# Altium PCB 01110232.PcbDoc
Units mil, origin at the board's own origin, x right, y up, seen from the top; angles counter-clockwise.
Board outline 3350 x 4325 mil, 2 copper layers (Top Layer, Bottom Layer); 124 components, 54 nets, 280 pads, 11 vias.
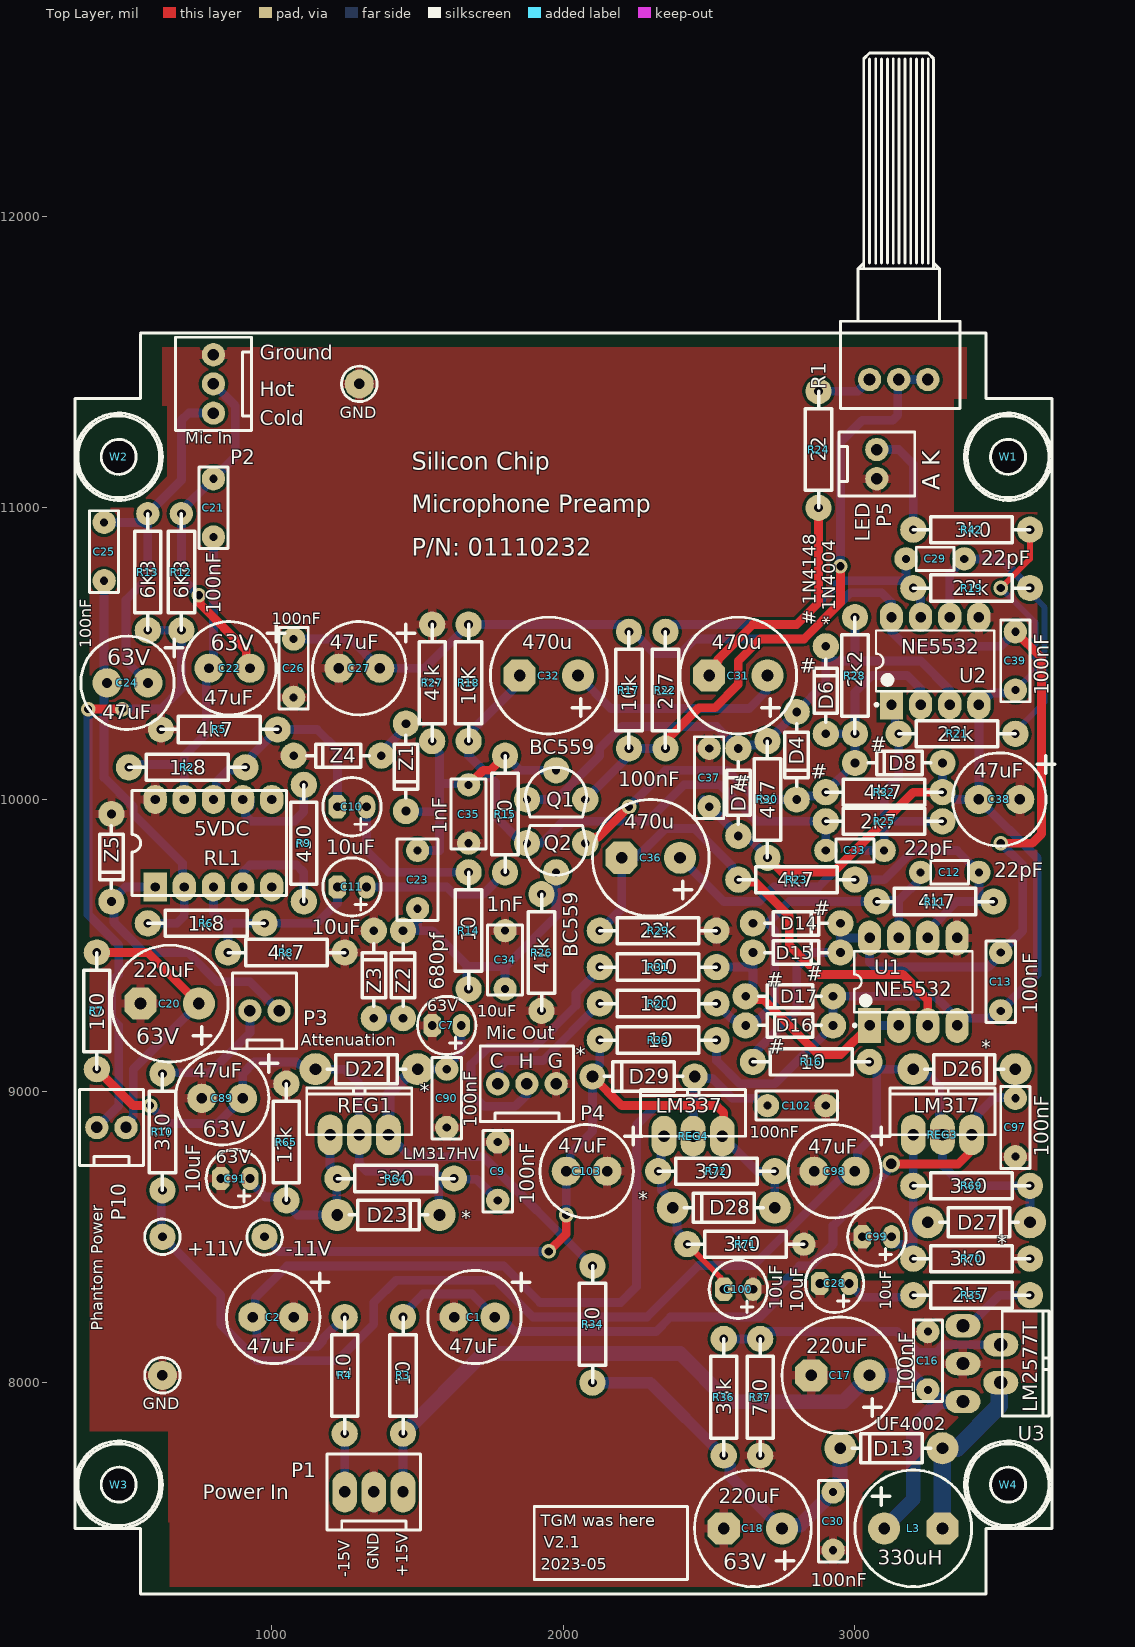
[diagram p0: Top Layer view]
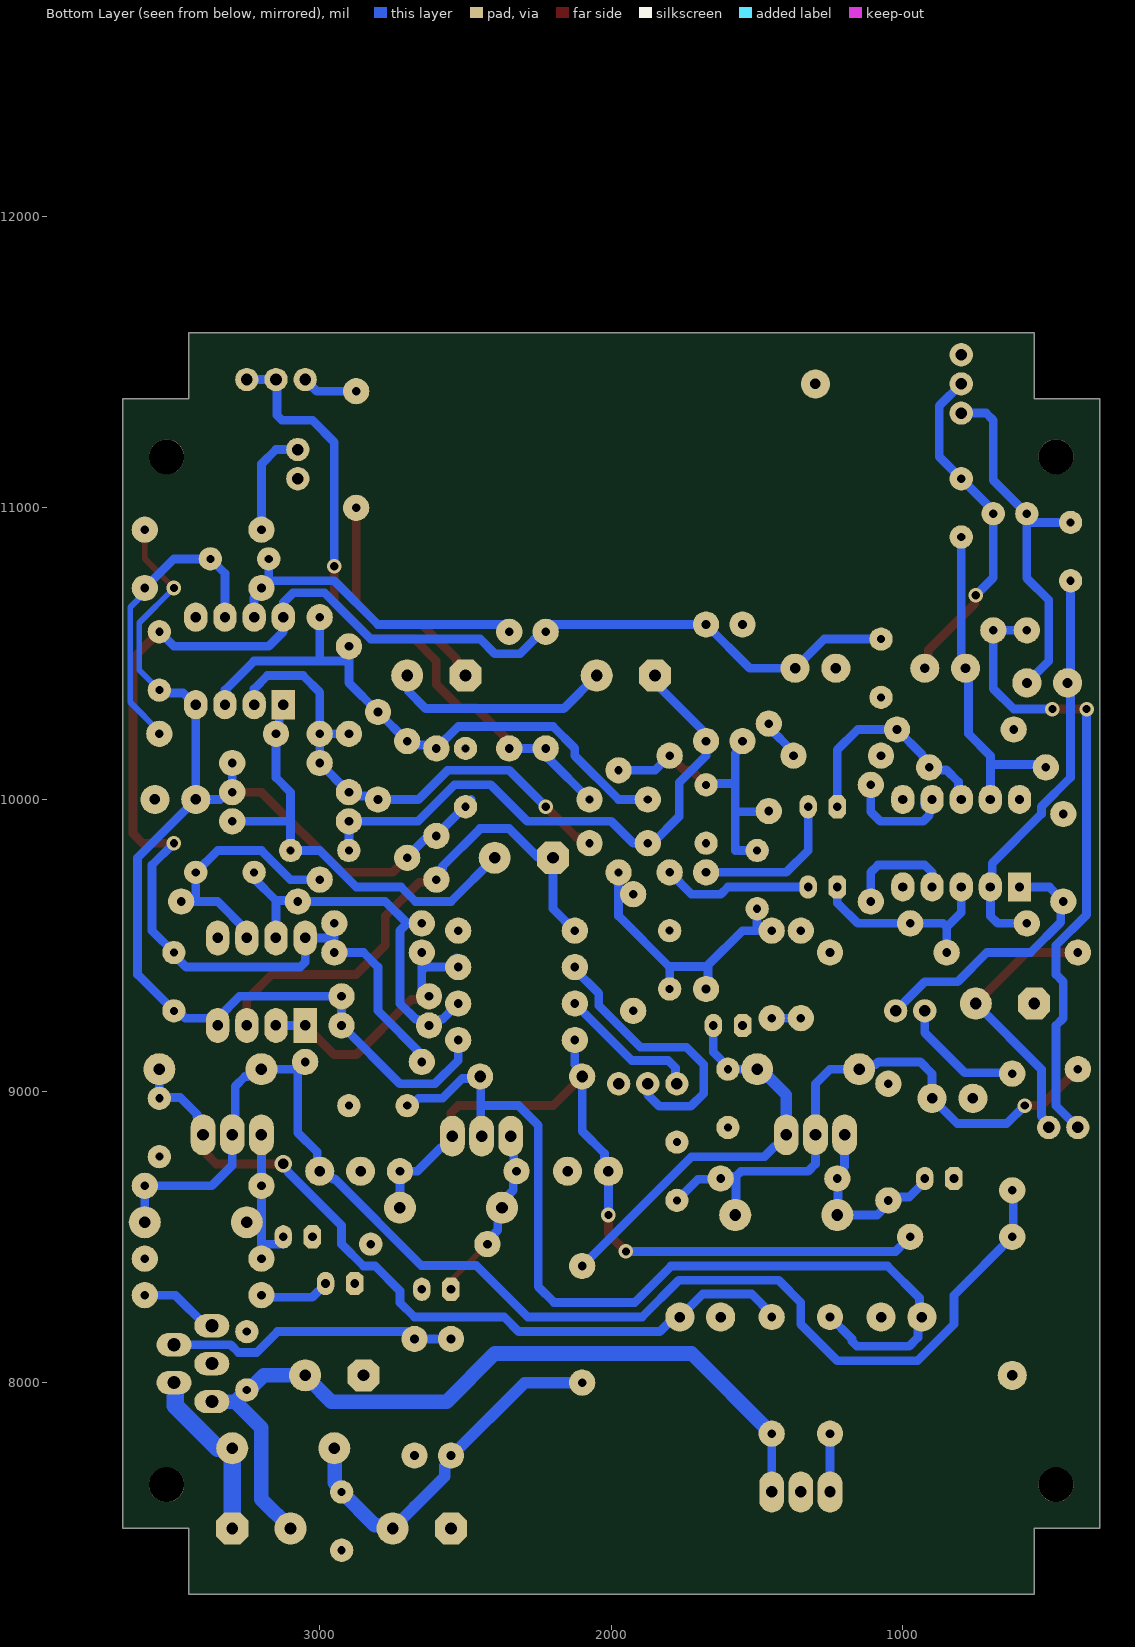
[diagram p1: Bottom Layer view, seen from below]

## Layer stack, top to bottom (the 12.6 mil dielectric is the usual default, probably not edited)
Top Solder: solder mask 0.4, Solder Resist, Dk 3.5
Top Layer: signal copper 1.4
Dielectric1: dielectric 12.6, FR-4, Dk 4.8
Bottom Layer: signal copper 1.4
Bottom Solder: solder mask 0.4, Solder Resist, Dk 3.5

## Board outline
325,7500 550,7500 550,7275 3450,7275 3450,7500 3675,7500 3675,11375 3450,11375 3450,11600 2800,11600 850,11600 550,11600 550,11375 325,11375

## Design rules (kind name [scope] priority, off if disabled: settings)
Clearance Clearance_1 [All] p1: gap=10 ignorepadtopadclearanceinfootprint=TRUE
Clearance Clearance_poly [(IsRegion)] p2: gap=10 ignorepadtopadclearanceinfootprint=FALSE
DiffPairsRouting [All] p1: maxlimit=10 minlimit=10 mostfreqgap=10 toplayer_minwidth=15 toplayer_maxwidth=15 toplayer_prefwidth=15 bottomlayer_minwidth=15 bottomlayer_maxwidth=15 bottomlayer_prefwidth=15 substack1={E4759729-C15E-44EF-B839-1660CB1699A4} toplayer_{e4759729-c15e-44ef-b839-1660cb1699a4}_minwidth=15 toplayer_{e4759729-c15e-44ef-b839-1660cb1699a4}_maxwidth=15 toplayer_{e4759729-c15e-44ef-b839-1660cb1699a4}_prefwidth=15 bottomlayer_{e4759729-c15e-44ef-b839-1660cb1699a4}_minwidth=15 bottomlayer_{e4759729-c15e-44ef-b839-1660cb1699a4}_maxwidth=15 bottomlayer_{e4759729-c15e-44ef-b839-1660cb1699a4}_prefwidth=15 substack2={AF7D8FCE-D8A9-40D7-8453-C7F108753530} toplayer_{af7d8fce-d8a9-40d7-8453-c7f108753530}_minwidth=15 toplayer_{af7d8fce-d8a9-40d7-8453-c7f108753530}_maxwidth=15 toplayer_{af7d8fce-d8a9-40d7-8453-c7f108753530}_prefwidth=15 bottomlayer_{af7d8fce-d8a9-40d7-8453-c7f108753530}_minwidth=15 bottomlayer_{af7d8fce-d8a9-40d7-8453-c7f108753530}_maxwidth=15 bottomlayer_{af7d8fce-d8a9-40d7-8453-c7f108753530}_prefwidth=15 maxuncoupledlength=500
Height [All] p1: minheight=0 maxheight=1130 prefheight=500
HoleSize [All] p1: absolutevalues=TRUE maxlimit=400 minlimit=1 maxpercent=80.000 minpercent=20.000
PlaneConnect [All] p1: planeconnectstyle=Relief reliefexpansion=20 reliefentries=4 reliefconductorwidth=30 reliefairgap=10
PolygonConnect [All] p1: connectstyle=Relief reliefconductorwidth=30 reliefentries=4 polygonreliefangle="90 Angle" airgapwidth=10
RoutingVias [All] p1: holewidth=16 width=32 viastyle="Through Hole" minholewidth=8 minwidth=16 maxholewidth=200 maxwidth=200
SilkToSolderMaskClearance SilkscreenOverComponentPads [IsPad] p1: minsilkscreentomaskgap=10 clearancetoexposedcopper=TRUE
SolderMaskExpansion [All] p1: expansion=4 istentingtop=FALSE
Width [All] p1: maxlimit=250 minlimit=10 preferedwidth=40 substack1={E4759729-C15E-44EF-B839-1660CB1699A4} substack2={AF7D8FCE-D8A9-40D7-8453-C7F108753530}
25 further rules are at their usual default settings.

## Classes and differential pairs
component class "Mic Interface": C10 C11 C12 C13 C20 C21 C22 C23 C24 C25 C26 C27 C29 C31 C32 C33 C34 C35 C36 C37 C38 C39 D4 D6 D7 D8 D14 D15 D16 D17 P2 P3 P4 P5 P10 Q1 Q2 R1 R2 R5 R6 R7 R8 R9 R10 R11 R12 R13 R14 R15 R16 R17 R18 R19 R20 R21 R22 R23 R24 R25 R26 R27 R28 R29 R30 R31 R32 R33 R42 RL1 U1 U2 Z1 Z2 Z3 Z4 Z5
component class "Power Supply": C1 C2 C7 C9 C16 C17 C18 C28 C30 C89 C90 C91 C97 C98 C99 C100 C102 C103 D13 D22 D23 D26 D27 D28 D29 F2 L3 L6 P1 R3 R4 R34 R35 R36 R37 R64 R65 R69 R70 R71 R72 REG1 REG3 REG4 U3 W1 W2 W3 W4

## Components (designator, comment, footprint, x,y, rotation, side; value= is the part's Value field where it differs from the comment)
C1 "47uF" RB3.5/8mm 1765,8225 r180 top
C2 "47uF" RB3.5/8mm 1075,8225 r180 top
C7 "10uF" RB.1/.2-PTH 1650,9225 r0 top
C9 "100nF" AXIAL0.2-2.5mm-CAP 1775,8625 r90 top
C10 "10uF" RB.1/.2-PTH 1325,9975 r0 top
C11 "10uF" RB.1/.2-PTH 1325,9700 r0 top
C12 "22pF" AXIAL0.2 3225,9750 r0 top
C13 "100nF" AXIAL0.2-2.5mm-CAP 3500,9475 r270 top
C16 "100nF" AXIAL0.2-2.5mm-CAP 3250,7975 r90 top
C17 "220uF" RB.2/.4 3050,8025 r0 top
C18 "220uF" RB.2/.4 2750,7500 r0 top
C20 "220uF" RB.2/.4 750,9300 r0 top
C21 "100nF" AXIAL0.2-2.5mm-CAP 800,11100 r270 top
C22 "47uF" RB3.5/8MM 925,10450 r180 top
C23 "680pf" AXIAL0.2-3.5mm-CAP 1500,9825 r270 top
C24 "47uF" RB3.5/8MM 575,10400 r180 top
C25 "100nF" AXIAL0.2-2.5mm-CAP 425,10950 r270 top
C26 "100nF" AXIAL0.2-2.5mm-CAP 1075,10550 r270 top
C27 "47uF" RB3.5/8mm 1370,10450 r180 top
C28 "10uF" RB.1/.2-PTH 2980,8340 r0 top
C29 "22pF" AXIAL0.2 3175,10825 r0 top
C30 "100nF" AXIAL0.2-2.5mm-CAP 2925,7625 r270 top
C31 "470u" RB.2/.4 2700,10425 r0 top
C32 "470u" RB.2/.4 2050,10425 r0 top
C33 "22pF" AXIAL0.2 2900,9825 r0 top
C34 "1nF" AXIAL0.2-CAP 1800,9550 r270 top
C35 "1nF" AXIAL0.2-CAP 1675,9850 r90 top
C36 "470u" RB.2/.4 2400,9800 r0 top
C37 "100nF" AXIAL0.2-2.5mm-CAP 2500,10175 r270 top
C38 "47uF" RB3.5/8mm 3565,10000 r180 top
C39 "100nF" AXIAL0.2-2.5mm-CAP 3550,10575 r270 top
C89 "47uF" RB3.5/8mm 900,8975 r180 top
C90 "100nF" AXIAL0.2-2.5mm-CAP 1600,9075 r270 top
C91 "10uF" RB.1/.2-PTH 925,8700 r0 top
C97 "100nF" AXIAL0.2-2.5mm-CAP 3550,8975 r270 top
C98 "47uF" RB3.5/8mm 3000,8725 r180 top
C99 "10uF" RB.1/.2-PTH 3125,8500 r0 top
C100 "10uF" RB.1/.2-PTH 2650,8320 r0 top
C102 "100nF" AXIAL0.2-2.5mm-CAP 2900,8950 r180 top
C103 "47uF" RB3.5/8mm 2150,8725 r180 top
D4 "1N914" "DIODE0.3-TH - AK" 2800,10300 r270 top
D6 "1N914" "DIODE0.3-TH - AK" 2900,10225 r90 top
D7 "1N914" "DIODE0.3-TH - AK" 2600,9875 r90 top
D8 "1N914" "DIODE0.3-TH - AK" 3300,10125 r180 top
D13 "UF4002" DIODE0.35-TH#1 3300,7775 r180 top
D14 "1N914" "DIODE0.3-TH - AK" 2650,9575 r0 top
D15 "1N914" "DIODE0.3-TH - AK" 2650,9475 r0 top
D16 "1N914" "DIODE0.3-TH - AK" 2925,9225 r180 top
D17 "1N914" "DIODE0.3-TH - AK" 2925,9325 r180 top
D22 "1N4004" DIODE0.35-TH#1 1150,9075 r0 top
D23 "1N4004" DIODE0.35-TH#1 1225,8575 r0 top
D26 "1N4004" DIODE0.35-TH#1 3200,9075 r0 top
D27 "1N4004" DIODE0.35-TH#1 3250,8550 r0 top
D28 "1N4004" DIODE0.35-TH#1 2725,8600 r180 top
D29 "1N4004" DIODE0.35-TH#2 2450,9050 r180 top
L3 "330uH" RB.2/.4 3100,7500 r180 top
P1 "Power In" "Header 3 SIL" 1450,7625 r180 top
P2 "Mic In" "HEADER 3 SIL" 800,11525 r270 top
P3 "Attenuation" "HEADER 2 SIL" 1025,9275 r180 top
P4 "Mic Out" "HEADER 3 SIL" 1975,9025 r180 top
P5 "LED" "Header 2 SIL" 3075,11100 r90 top
P10 "Phantom Power" "HEADER 2 SIL" 500,8875 r180 top
Q1 "BC559" TO-92BIG 1975,10100 r90 top
Q2 "BC559" TO-92BIG 1975,9750 r270 top
R1 "10K Reverse Log" "POT_Small_Single - TT Single Horizontal" 3150,11440 r180 top
R2 "1k8" AXIAL0.4#1 910,10110 r180 top
R3 "10" AXIAL0.4#1 1450,7825 r90 top
R4 "10" AXIAL0.4#1 1250,8225 r270 top
R5 "4k7" AXIAL0.4#1 1020,10240 r180 top
R6 "1k8" AXIAL0.4#1 975,9575 r180 top
R7 "100" AXIAL0.4#1 400,9075 r90 top
R8 "4k7" AXIAL0.4#1 850,9475 r0 top
R9 "430" AXIAL0.4#1 1110,10050 r270 top
R10 "330" AXIAL0.4#1 625,9059.69 r270 top
R11 "4k7" AXIAL0.4#1 3075,9650 r0 top
R12 "6K8" AXIAL0.4#2 690,10980 r270 top
R13 "6K8" AXIAL0.4#2 575,10980 r270 top
R14 "10" AXIAL0.4#1 1675,9750 r270 top
R15 "10" AXIAL0.4#1 1800,9750 r90 top
R16 "10" AXIAL0.4#1 3050,9100 r180 top
R17 "10k" AXIAL0.4#1 2225,10175 r90 top
R18 "10K" AXIAL0.4#1 1675,10200 r90 top
R19 "22k" AXIAL0.4#1 3200,10725 r0 top
R20 "100" AXIAL0.4#1 2525,9300 r180 top
R21 "22k" AXIAL0.4#1 3550,10225 r180 top
R22 "2k7" AXIAL0.4#1 2350,10175 r90 top
R23 "4k7" AXIAL0.4#1 3000,9725 r180 top
R24 "22" AXIAL0.4#1 2875,11400 r270 top
R25 "2k7" AXIAL0.4#1 2900,9925 r0 top
R26 "47k" AXIAL0.4#1 1925,9675 r270 top
R27 "47k" AXIAL0.4#1 1550,10200 r90 top
R28 "2k2" AXIAL0.4#1 3000,10625 r270 top
R29 "22k" AXIAL0.4#1 2525,9550 r180 top
R30 "4K7" AXIAL0.4#1 2700,9800 r90 top
R31 "100" AXIAL0.4#1 2525,9425 r180 top
R32 "4K7" AXIAL0.4#1 3300,10025 r180 top
R33 "10" AXIAL0.4#1 2125,9175 r0 top
R34 "10" AXIAL0.4#1 2100,8000 r90 top
R35 "2k7" AXIAL0.4#1 3200,8300 r0 top
R36 "33k" AXIAL0.4#1 2550,8150 r270 top
R37 "750" AXIAL0.4#1 2675,7750 r90 top
R42 "3k0" AXIAL0.4#1 3200,10925 r0 top
R64 "330" AXIAL0.4#1 1225,8700 r0 top
R65 "12k" AXIAL0.4#1 1050,9025 r270 top
R69 "390" AXIAL0.4#1 3200,8675 r0 top
R70 "3k0" AXIAL0.4#1 3600,8425 r180 top
R71 "3k0" AXIAL0.4#3 2425,8475 r0 top
R72 "390" AXIAL0.4#1 2725,8725 r180 top
REG1 "LM317HV" TO-220-REG 1300,8850 r0 top
REG3 "LM317" TO-220-REG 3300,8850 r0 top
REG4 "LM337" TO-220-REG 2444.99,8845 r0 top
RL1 "5VDC" DIP10 600,9700 r90 top
U1 "NE5532" DIP-8#1 3200,9375 r90 top
U2 "NE5532" DIP-8#2 3275,10475 r90 top
U3 "LM2577T" "TO-220 - 5PIN" 3520,8065 r270 top
W1 "Washer" "M3 Crinkle" 3525,11175 r0 top
W2 "Washer" "M3 Crinkle" 475,11175 r0 top
W3 "Washer" "M3 Crinkle" 475,7650 r0 top
W4 "Washer" "M3 Crinkle" 3525,7650 r0 top
Z1 "6V8" "DIODE0.3-TH - AK" 1460,10260 r270 top
Z2 "6V8" "DIODE0.3-TH - AK" 1450,9250 r90 top
Z3 "6V8" "DIODE0.3-TH - AK" 1350,9250 r90 top
Z4 "6V8" "DIODE0.3-TH - AK" 1375,10150 r180 top
Z5 "6V8" "DIODE0.3-TH - AK" 450,9950 r270 top

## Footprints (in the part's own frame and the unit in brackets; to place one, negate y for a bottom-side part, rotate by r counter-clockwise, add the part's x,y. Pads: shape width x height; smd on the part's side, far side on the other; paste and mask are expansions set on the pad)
AXIAL0.2 [mil]
  round 80 hole 28: 1(0,0) 2(200,0)
  silkscreen extent 35,-40 165,40, body extent 30,-45 170,45, height 200
AXIAL0.2-2.5mm-CAP [mil]
  round 80 hole 28: 1(0,0) 2(200,0)
  silkscreen extent -40,-50 240,50, body extent -40,-50 240,50, height 200
AXIAL0.2-3.5mm-CAP [mil]
  round 80 hole 28: 1(0,0) 2(200,0)
  silkscreen extent -40,-70 240,70, body extent -40,-70 240,70, height 200
AXIAL0.2-CAP [mil]
  round 80 hole 28: 1(0,0) 2(200,0)
  silkscreen extent -20,-60 220,60, body extent -25,-65 225,65, height 200
AXIAL0.4#1 [mil] "resistor"
  round 90 hole 30: 1(0,0) 2(400,0)
  silkscreen extent 0,-45 400,45, body extent -5,-50 405,50, height 100
AXIAL0.4#2 [mil] "resistor"
  round 80 hole 30: 1(0,0)
  round 90 hole 30: 2(400,0)
  silkscreen extent 0,-45 400,45, body extent -5,-50 405,50, height 100
AXIAL0.4#3 [mil] "resistor"
  round 90 hole 30: 1(0,0)
  round 80 hole 30: 2(400,0)
  silkscreen extent 0,-45 400,45, body extent -5,-50 405,50, height 100
"DIODE0.3-TH - AK" [mil] "DO-35 Footprint"
  round 90 hole 30: A(0,0) K(300,0)
  silkscreen extent 40,-40 255,40, body extent -15,-40 315,40, height 95
DIODE0.35-TH#1 [mil]
  round 110 hole 40: 1(0,0) 2(350,0)
  silkscreen extent 40,-50 310,50, body extent -15,-55 365,55, height 110
DIODE0.35-TH#2 [mil]
  round 90 hole 40: 1(0,0) 2(350,0)
  silkscreen extent 40,-50 310,50, body extent -15,-55 365,55, height 110
DIP10 [mil] "DPDT signal relay"
  rect 100x80 hole 32: 1(0,0)
  oval 100x80 hole 32: 2(0,-100) 3(0,-200) 4(0,-300) 5(0,-400) 6(300,-400) 7(300,-300) 8(300,-200) 9(300,-100) 10(300,0)
  silkscreen extent -30,-450 330,80, body extent -30,-450 330,80, height 300
DIP-8#1 [mil] "DIP; 8 Leads; Row Spacing 7.62 mm; Pitch 2.54 mm"
  rect 120x80 hole 36: 1(-150,150)
  oval 120x80 hole 36: 2(-150,50) 3(-150,-50) 4(-150,-150) 5(150,-150) 6(150,-50) 7(150,50) 8(150,150)
  silkscreen extent -155,-203 104,206, body extent -142,-203 142,203, height 200
DIP-8#2 [mil] "DIP; 8 Leads; Row Spacing 7.62 mm; Pitch 2.54 mm"
  rect 100x80 hole 35.43: 1(-150,150)
  oval 100x80 hole 35.43: 2(-150,50) 3(-150,-50) 4(-150,-150) 5(150,-150) 6(150,-50) 7(150,50) 8(150,150)
  silkscreen extent -155,-203 104,206, body extent -142,-203 142,203, height 200
"HEADER 2 SIL" [mil] "Altronics P5494"
  round 80 hole 39.37: 1(0,0) 2(100,0)
  silkscreen extent -60,-130 160,130, body extent -65,-135 160,135, height 460
"Header 2 SIL" [mil] "Altronics P5494"
  round 80 hole 39.37: 1(0,0) 2(100,0)
  silkscreen extent -60,-130 160,130, body extent -65,-135 160,135, height 460
"Header 3 SIL" [mil] "Altronics P5494"
  oval 85x140 hole 39.37: 1(0,0) 2(100,0) 3(200,0)
  silkscreen extent -60,-130 260,130, body extent -65,-135 260,135, height 460
"HEADER 3 SIL" [mil] "Altronics P5494"
  round 80 hole 39.37: 1(0,0) 2(100,0) 3(200,0)
  silkscreen extent -60,-130 260,130, body extent -65,-135 260,135, height 460
"M3 Crinkle" [mil] "M3 Crinkle Washer"
  silkscreen extent -140,-140 140,140, body extent -140,-140 140,140, height 20
"POT_Small_Single - TT Single Horizontal" [mil] "Bourns PTV111-1 Single Turn Small"
  round 80 hole 40: 1(-100,0) 2(0,0) 3(100,0)
  silkscreen extent -210,-1120 200,100, body extent -210,-1125 200,100, height 500
RB3.5/8mm [mil]
  round 100 hole 36: 1(0,0) 2(140,0)
  silkscreen extent -120,-160 230,160, body extent -90,-160 230,160, height 450
RB3.5/8MM [mil]
  round 100 hole 34: 1(0,0) 2(140,0)
  silkscreen extent -120,-160 230,160, body extent -90,-160 230,160, height 450
RB.1/.2-PTH [mil]
  oval 60x80 hole 30: 1(0,0)
  oct 60x80 hole 30: 2(-100,0)
  silkscreen extent -150,-100 50,100, body extent -150,-100 50,100, height 300
RB.2/.4 [mil]
  round 110 hole 40: 1(0,0)
  oct 110x110 hole 40: 2(-200,0)
  silkscreen extent -300,-200 100,200, body extent -300,-200 100,200, height 1000
TO-92BIG [mil]
  round 90 hole 28: B(0,0) C(-100,100) E(-100,-100)
  silkscreen extent -160,-105 10,105, body extent -160,-110 10,110, height 500
"TO-220 - 5PIN" [mil]
  oval 80x120 hole 45: 1(-130,-150) 2(-65,-20) 3(0,-150) 4(65,-20) 5(130,-150)
  silkscreen extent -180,-15 180,145, body extent -180,-160 180,145, height 950
TO-220-REG [mil]
  oval 85x140 hole 40: 1(-100,0) 2(-0.12,0.2) 3(100,0)
  silkscreen extent -180,0 180,160, body extent -180,0 180,160, height 800

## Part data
C1 C2 C27 C38 C89 C98 C103: library part "CAPACITOR POL", "Altronics p/n R5108"
C7 C91: library part CAPACITOR, "Altronics p/n R4768"
C9 C13 C16 C21 C25 C26 C30 C37 C39 C90 C97 C102: library part CAP, "Altronics p/n R3025B"
C10 C11 C28 C99 C100: library part CAPACITOR, "Altronics p/n R6067"
C12 C29 C33: library part CAP, "Altronics p/n R2814"
C17 C18 C20: library part "CAPACITOR POL", "Altronics p/n R5148"
C22 C24: library part CAPACITOR, "Altronics p/n R5108"
C23: library part CAP, "Mouser p/n 810-FA28C0G1H68100"
C31 C32 C36: library part CAPACITOR, "Altronics p/n R5164"
C34 C35: library part CAP, "Altronics p/n R3001B"
D4 D6 D7 D8 D14 D15 D16 D17: library part DIODE, "Altronics p/n Z0101"
D13: library part DIODE_Numbered, "Altronics p/n Z0030"
D22 D26: library part DIODE_Numbered, "Altronics p/n Z0109"
D23 D27 D28 D29: library part DIODE, "Altronics p/n Z0109"
L3: library part INDUCTOR, "Altronics p/n L6227"
P1 P2 P4: library part "Header 3", "Altronics p/n  P5493 + P5473"
P3 P5 P10: library part CON2, "Altronics p/n  P5492 + P5472"
Q1 Q2: library part PNP, "Altronics p/n Z1057"
R1: library part POT-SINGLE, "Mouser p/n  858-P091NFC25CR10K or 652-PTD9012015FC103"
R2 R6: library part RES2, "Altronics p/n R7564"
R3 R4 R34: library part RES2, "Altronics p/n Z7510"
R5 R8 R11 R23 R30 R32: library part RES2, "Altronics p/n R7574"
R7: library part RES2, "Altronics p/n Z7534"
R9: library part RES2, "Altronics p/n R7551"
R10: library part RES2, "Altronics p/n R7538"
R12 R13: library part RES2, "Altronics p/n R7778"
R14 R15 R16 R33: library part RES2, "Altronics p/n R7510"
R17 R18: library part RES2, "Altronics p/n R7582"
R19 R21 R29: library part RES2, "Altronics p/n R7590"
R20 R31: library part RES2, "Altronics p/n R7534"
R22 R25 R35: library part RES2, "Altronics p/n R7568"
R24: library part RES2, "Altronics p/n R7518"
R26 R27: library part RES2, "Altronics p/n R7598"
R28: library part RES2, "Altronics p/n R7566"
R36: library part RES2, "Altronics p/n R7594"
R37: library part RES2, "Altronics p/n R7555"
R42 R70 R71: library part RES2, "Altronics p/n R7569"
R64: library part RES2, "Altronics p/n R7546"
R65: library part RES2, "Altronics p/n R7584"
R69 R72: library part RES2, "Altronics p/n R7548"
REG1: library part LM317, "Altronics p/n Z0545"
REG3: "Altronics p/n Z0545"
REG4: "Altronics p/n Z0562"
RL1: library part RELAY-DPDT_OMRON, "Altronics p/n S4128B"
U1 U2: library part LF353, "Altronics p/n Z2785"
U3: library part LM2577T-ADJ/NOPB, "Jaycar p/n ZV1640", Manufacturer="National Semiconductor", PackageTopMarking=NSUZXYTTE#*LM2577T*-ADJ*P+, PowerWise=N, Supplier Part Number 1=LM2577T-ADJ-ND
W1 W2 W3 W4: "Altronics p/n H3185"
Z1 Z2 Z3 Z4 Z5: library part ZENER2, "Altronics p/n Z0320"

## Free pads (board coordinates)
  round 120 hole 120: 3(475,7650) 3(475,11175) 3(3525,7650) 3(3525,11175)
  round 100 hole 36: 4(625,8025) 4(1300,11425)
  round 90 hole 30: 6(625,8500) 7(975,8500)

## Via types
v1: diameter 50, hole 28, Top Layer to Bottom Layer, 10 vias
v2: diameter 60, hole 36, Top Layer to Bottom Layer, 1 vias

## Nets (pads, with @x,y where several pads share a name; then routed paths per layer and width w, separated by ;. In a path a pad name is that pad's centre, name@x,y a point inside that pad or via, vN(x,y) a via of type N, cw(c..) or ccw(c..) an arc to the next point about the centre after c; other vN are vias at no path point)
48V: C9.1 C89.1 D22.1 D23.2 R7.1 R64.2 REG1.2 | length 2080.7
  Top Layer w30: R7.1 525,8950 v1(582.37,8950)
  Bottom Layer w30: v1(582.37,8950) 643.84,8888.53 813.53,8888.53 C89.1 900,9059.69 940.31,9100 1084.61,9100 1094.3,9090.31 1134.69,9090.31 D22.1 1250,9075 1299.88,9025.12 REG1.2 1299.88,8750.12 1325,8725 1554.93,8725 1572.5,8707.43 ; D23.2 1572.5,8577.5 1572.5,8707.43 ; C9.1 1702.5,8697.5 1627.5,8697.5 R64.2 1617.57,8707.43 1572.5,8707.43
+DC_In: C16.1 C17.1 L3.1 P1.1 R3.1 U3.5 | length 2874.4
  Bottom Layer w30: P1.1 R3.1
  Bottom Layer w50: R3.1 1725,8100 2400,8100 2565,7935 2960,7935 3035,8010 C17.1@3040,8010 ; C17.1 3191.88,8025 3241.88,7975 C16.1 3250,7974.48 3289.48,7935 ; L3.1 3200,7600 3200,7845.52 3289.48,7935 ; U3.5 3289.48,7935
+V_filt_2: C13.1 C26.1 C27.1 C39.1 D14.K D15.K R16.2 R17.2 R18.2 U1.8 U2.8 | length 5510.6
  Top Layer w30: U2.8 U2.8@3125,10635 ; v1(3500,9850) 3607.57,9850 3640,9882.43 3640,10485 C39.1
  Bottom Layer w30: C26.1 1270,10550 C27.1 ; C27.1@1375,10450 1525,10450 R18.2 2225,10600 2225,10588.39 2313.39,10500 2400,10500 2450,10550 2825,10550 2983.76,10708.76 3091.24,10708.76 3125,10675 U2.8 3125,10575 3175,10525 3500,10525 C39.1 ; R16.2@2637.38,9121.14 2646.14,9121.14 2800,9275 2800,9425 2850,9475 D15.K 2950,9525 ; D14.K 2950,9525 ; U2.8@3146.66,10628.34 U2.8@3150,10625 ; v1(3500,9850) 3575,9775 3575,9550 C13.1 3500,9467.57 3457.43,9425 3067.57,9425 3050,9442.57 U1.8 2950,9525
+VREG: C98.1 D26.1 D27.2 pad.6 R10.2 R16.1 R69.2 REG3.2 | length 4575.4
  Bottom Layer w30: R10.2 621.21,8655.9 621.21,8503.79 825,8300 825,8200 950,8075 1225,8075 1350,8200 1350,8275 1426.3,8351.3 1768.66,8351.3 1894.96,8225 2286.48,8225 2463.23,8401.75 2651.75,8401.75 2948.65,8698.65 2954.71,8698.65 2981.06,8725 C98.1 3008.69,8733.69 3008.69,8790.66 3075,8856.98 R16.1@3075,9075 ; R16.1 R16.1@3075,9075 ; D27.2 R69.2 3370,8675 3300,8745 3300,8850 3289.48,8860.52 3289.48,9016.77 3256.34,9049.91 3246.73,9049.91 3221.65,9075 D26.1 R16.1@3075,9075
-DC_In: P1.3 R4.2 | length 200
  Bottom Layer w30: P1.3 R4.2
-V_filt_2: C13.2 C37.2 C38.2 C39.2 D7.A D8.A D16.A D17.A R30.1 R32.1 R33.2 R42.2 U1.4 U2.4 | length 4629.4
  Top Layer w20: v1(3500,10725) 3600,10825 R42.2
  Top Layer w30: R30.1 2750,9750 2925,9750 3200,10025 R32.1 ; D16.A@2925,9210 D16.A
  Bottom Layer w20: v1(3500,10725) 3618.75,10606.25 3618.75,10443.75 C39.2
  Bottom Layer w30: C37.2@2480,10000 2480,9997.5 2600,9877.5 D7.A 2611.48,9863.52 2640.24,9863.52 2700,9803.76 R30.1 ; R33.2 2525,9104.96 2604.96,9025 2725,9025 D16.A D17.A 3275,9325 3350,9250 U1.4@3350,9226.9 ; D8.A R32.1 3316.24,10025 3341.24,10000 C38.2 ; U1.4 U1.4@3350,9226.9 ; C39.2 3540.43,10365.43 3468.96,10365.43 3428.53,10325 U2.4 C38.2 ; U1.4@3350,9226.9 3373.1,9250 3461.47,9250 3486.47,9275 C13.2 3625,9400 3625,9800 C38.2
-VREG: C103.2 D28.1 D29.2 pad.7 R33.1 R72.1 REG4.3 | length 2774.2
  Top Layer w30: v1(1950,8450) 2010,8510 v1(2010,8575) ; D29.2 2200,8950 2525,8950 2550,8925 2550,8850.01 REG4.3
  Bottom Layer w30: pad.7 1025,8450 v1(1950,8450) ; v1(2010,8575) C103.2 2023.39,8738.39 2023.39,8785.78 2100,8862.38 D29.2 2100,9066.24 2125,9091.24 R33.1 ; REG4.3@2544.99,8880.01 REG4.3 2544.99,8832.38 2570.4,8806.98 2583.01,8806.98 2664.99,8725 R72.1 D28.1
C: C24.1 C25.1 P2.3 R13.1 | length 1280.1
  Bottom Layer w30: C25.1 R13.1@575,10950 ; C24.1 500,10475 500,10683.76 575,10758.76 R13.1@575,10950 ; P2.3 715,11325 690,11300 690,11095 R13.1 R13.1@575,10950
GND: C1.2 C2.1 C7.2 C9.2 C16.2 C17.2 C18.2 C20.2 C26.2 C27.2 C28.2 C30.2 C34.1 C35.1 C37.1 C38.1 C89.2 C90.2 C91.2 C97.2 C98.2 C99.2 C100.1 C102.1 C103.1 P1.2 P2.1 P4.1 P5.1 pad.4 R5.2 R8.2 R26.2 R27.2 R29.1 R37.1 R65.1 R70.1 R71.2 RL1.10 U1.5 U2.5 U3.3 Z3.K Z4.K Z5.A
H: C21.1 C22.1 P2.2 R12.1 | length 1180
  Top Layer w30: v1(750,10700) 753.83,10696.17 753.83,10671.17 912.82,10512.18 912.82,10462.18 C22.1
  Bottom Layer w30: v1(750,10700) 690,10760 690,10990 C21.1 875,11175 875,11350 P2.2
MIC: C36.2 R23.2 R29.2 U1.3 | length 1777.2
  Top Layer w30: R23.2 2608.64,9716.36 2658.64,9716.36 2775,9600 2775,9500 2875,9400 3163.52,9400 3250,9313.52 U1.3
  Bottom Layer w30: R29.2 2200,9625 C36.2 2250,9800 2350,9900 2450,9900 2578.86,9771.14 2578.86,9762.38 2600,9741.24 R23.2
Mic_Out_C: P4.3 R20.2 | length 493.2
  Bottom Layer w30: P4.3 1780.1,9030.1 1780.1,9080.1 1804.96,9104.96 1929.96,9104.96 R20.2
Mic_Out_H: P4.2 R31.2 | length 973
  Bottom Layer w30: P4.2 1875,9002.8 1875,8987.37 1835.23,8947.6 1727.4,8947.6 1683.18,8991.82 1683.18,9091.24 1741.94,9150 1900,9150 2043.5,9293.5 2043.5,9335.25 2125,9416.76 R31.2
NetC1_1: C1.1 C97.1 D26.2 R3.2 REG3.3 | length 2754.2
  Top Layer w30: v2(3125,8750) 3354.33,8750 3389.48,8785.15 3389.48,8839.48 REG3.3
  Bottom Layer w30: R3.2 1450,8235.07 1518.73,8303.8 1686.2,8303.8 C1.1 1783.94,8225 1833.94,8175 2317.57,8175 2367.57,8225 2675,8225 2725,8275 2725,8315 2810,8400 2850,8400 2925,8475 2925,8538.53 3110,8723.53 3110,8726.88 3125,8741.88 v2(3125,8750) ; REG3.3 3400,8892.38 3420.62,8913 3420.62,8920.62 3478.02,8978.02 3546.98,8978.02 C97.1 D26.2
NetC2_2: C2.2 C102.2 D29.1 R4.1 REG4.2 | length 3212.5
  Top Layer w30: REG4.2 REG4.2@2447.44,8847.76 ; D29.1@2447.44,9047.44 D29.1
  Bottom Layer w30: R4.1 1175,8150 1175,8142.57 1157.43,8125 978.52,8125 948.39,8155.13 948.39,8211.61 C2.2 943.46,8233.46 943.46,8290.89 1052.57,8400 1794.96,8400 1919.96,8275 2196.2,8275 2250.43,8329.23 2250.43,8882.86 2317.57,8950 2445.04,8950 2447.44,8947.6 ; REG4.2 2447.44,8847.76 2447.44,8947.6 ; D29.1@2447.44,9047.44 2447.44,8947.6 ; D29.1 2456.71,9043.29 2510.57,9043.29 2578.86,8975 2661.47,8975 2686.47,8950 C102.2
NetC7_1: C7.1 C90.1 D22.2 R34.2 REG1.3 | length 1420.6
  Bottom Layer w30: REG1.3 1400,8837.38 1425.41,8811.98 1438.02,8811.98 1475,8775 1725,8775 R34.2 ; D22.2 C90.1 1600,9083.76 1650,9133.76 C7.1
  Bottom Layer w40: REG1.3 1400,8987.37 1475,9062.37 D22.2@1475,9075
NetC10_1: C10.1 R14.1 | length 531.1
  Bottom Layer w30: C10.1 1325,9825 1400,9750 R14.1
NetC10_2: C10.2 R2.1 R5.1 RL1.8 | length 789.5
  Bottom Layer w30: RL1.8 809.57,10009.57 809.57,10059.57 851.36,10101.36 901.36,10101.36 R2.1 910,10126.24 933.82,10150.05 933.82,10153.46 1020,10239.64 R5.1 1155.1,10240 1225,10170.1 C10.2
NetC11_1: C11.1 R15.1 | length 516.4
  Bottom Layer w30: C11.1 1600,9700 1625,9675 1725,9675 R15.1
NetC11_2: C11.2 R6.1 R8.1 RL1.3 | length 710
  Bottom Layer w30: RL1.3 800,9612.37 850,9562.37 ; R8.1 850,9562.37 ; C11.2 1225,9644.9 1155.1,9575 R6.1 862.63,9575 850,9562.37
NetC12_1: C12.1 D14.A D16.K R11.1 R20.1 U1.7 | length 1344.8
  Bottom Layer w30: R20.1@2525,9325 2536.48,9313.52 2536.48,9288.52 2578.86,9246.14 2587.62,9246.14 2608.76,9225 D16.K ; D16.K@2641.24,9225 2662.38,9246.14 2671.14,9246.14 2725,9300 2725,9550 2700,9575 ; D14.A 2700,9575 ; U1.7 3150,9653.53 ; C12.1 3225,9728.53 3150,9653.53 ; 2700,9575 2775,9650 R11.1 3078.53,9653.53 3150,9653.53
NetC12_2: C12.2 R11.2 R23.1 U1.6 | length 888.9
  Bottom Layer w30: R23.1 3100,9725 3200,9825 3350,9825 C12.2 3425,9650 ; U1.6 3250,9550 3350,9650 3425,9650 ; R11.2 3425,9650
NetC18_1: C18.1 C30.1 D13.2 R34.1 R36.2 | length 1273.5
  Bottom Layer w40: R34.1 2297.44,8000 2547.44,7750 R36.2 2550,7736.47 2571.75,7714.72 2571.75,7678.25 2675,7575 C18.1
  Bottom Layer w50: C18.1 2761.48,7511.48 2811.48,7511.48 C30.1 2925,7633.12 2948.65,7656.77 2948.65,7756.52 2950,7757.87 D13.2
NetC20_1: C20.1 P10.1 R7.2 | length 967.3
  Top Layer w30: R7.2 575,9475 C20.1
  Bottom Layer w30: R7.2 R7.2@400,9491.24 ; P10.1 500,8888.53 525,8913.53 525,9075 C20.1
NetC21_2: C21.2 C22.2 R2.2 RL1.9 | length 1139.7
  Bottom Layer w30: R2.2 520,10120 700,10120 ; RL1.9 700,10120 ; C22.2@775,10450 800,10475 C21.2 ; C22.2 775,10440 775,10225 700,10150 700,10120
NetC23_1: C23.1 C35.2 Q1.B R15.2 R27.1 Z1.K | length 1095.1
  Top Layer w30: C35.2 1725,10100 1750,10100 R15.2
  Bottom Layer w30: Z1.K 1462.47,9957.53 1575,9957.53 ; C23.1@1475,9825 1563.52,9825 1575,9836.48 ; R27.1 1550,10183.76 1575,10158.76 1575,10054.38 ; 1575,9825 1575,9836.48 ; C35.2@1675,10075 C35.2 1670.62,10054.38 1575,10054.38 ; R15.2 1850,10100 Q1.B ; 1575,9836.48 1575,9957.53 ; 1575,9957.53 1575,10054.38
NetC23_2: C23.2 C34.2 Q2.B R14.2 R26.1 Z2.K | length 1072.7
  Bottom Layer w30: Z2.K@1450,9562.5 Z2.K 1500,9550 ; C23.2 1500,9550 ; R14.2 1668.75,9356.25 1668.75,9426.98 ; C34.2 1800,9426.98 ; R26.1 1975,9675 ; Q2.B@1975,9728.53 1975,9675 ; 1500,9550 1550,9550 1668.75,9431.25 1668.75,9426.98 ; 1668.75,9426.98 1800,9426.98 ; 1800,9426.98 1801.98,9426.98 1975,9600 1975,9675
NetC24_2: C24.2 C25.2 R6.2 RL1.2 | length 1403.4
  Bottom Layer w30: C24.2@425,10425 425,10075 525,9975 525,9950 693.63,9781.37 693.63,9706.37 RL1.2 700,9600 675,9575 R6.2 ; C25.2 425,10435 C24.2@435,10425
NetC28_1: C28.1 R35.1 | length 251.4
  Bottom Layer w30: C28.1 2980,8338.12 3025.62,8292.5 3192.5,8292.5 R35.1 R35.1@3200,8292.5
NetC29_1: C29.1 R19.1 R22.2 U2.7 | length 1132.9
  Bottom Layer w30: R22.2@2350,10600 2800,10600 2950,10750 3175,10750 R19.1 ; R19.1@3175,10741.88 C29.1 ; R19.1@3191.88,10725 3225,10691.88 U2.7 ; U2.7@3240.43,10634.57 U2.7@3250,10625
NetC29_2: C29.2 R19.2 R21.1 U2.6 | length 1049.3
  Bottom Layer w20: R21.1@3550,10233.12 3650,10333.12 3650,10658.76 R19.2@3600,10708.76
  Bottom Layer w30: U2.6 3325,10775 C29.2 3500,10825 R19.2 R19.2@3600,10708.76 ; R21.1 R21.1@3550,10233.12
NetC31_1: C31.1 C32.1 | length 793.8
  Bottom Layer w30: C32.1 2163.52,10311.48 2636.48,10311.48 2696.79,10371.79 C31.1@2696.79,10446.79
NetC31_2: C31.2 R24.2 | length 822.1
  Top Layer w30: C31.2 2500,10443.71 2530.57,10474.28 2530.57,10480.57 2650,10600 2800,10600 2875,10675 R24.2@2875,11003.86
NetC32_2: C32.2 C33.1 Q2.E R18.1 R25.1 | length 1974.5
  Bottom Layer w30: C32.2 1850,10400 1675,10225 R18.1 1675,10150 1766.94,10058.06 1766.94,9941.82 1858.76,9850 Q2.E ; Q2.E@1900,9850 1925,9850 2000,9925 2125,9925 2288.52,9925 2413.52,10050 2537.95,10050 2662.95,9925 R25.1 C33.1
NetC33_2: C33.2 C36.1 R21.2 R25.2 U2.1 | length 1565.7
  Bottom Layer w30: C36.1 2550,9650 2671.47,9650 2721.47,9700 2875,9700 3000,9825 C33.2 3100,9925 ; U2.1 3138.52,10311.48 3138.52,10236.48 R21.2 3150,10075 3100,10025 3100,9925 ; R25.2 3100,9925
NetC91_1: C91.1 D23.1 R64.1 R65.2 REG1.1 | length 644.1
  Bottom Layer w30: C91.1 925,8690 978.52,8636.48 1038.52,8636.48 R65.2 ; R65.2@1046.56,8616.82 1088.38,8575 D23.1@1222.5,8575 ; REG1.1 1200,8741.24 1225,8716.24 R64.1 1222.5,8697.5 D23.1@1222.5,8575 ; D23.1 D23.1@1222.5,8575
NetC99_1: C99.1 D27.1 R69.1 R70.2 REG3.1 | length 550
  Bottom Layer w30: C99.1@3125,8475 3200,8475 ; R70.2 3200,8475 ; REG3.1 R69.1 D27.1@3200,8550 ; D27.1 D27.1@3200,8550 ; 3200,8475 D27.1@3200,8550
NetC100_2: C100.2 D28.2 R71.1 R72.2 REG4.1 | length 622.3
  Top Layer w20: R71.1 2539.14,8360.86 2539.14,8330.86 C100.2
  Bottom Layer w30: REG4.1@2335,8810.78 2335,8735 R72.2 2336.48,8713.52 2336.48,8660.17 2375,8621.65 D28.2 2389.65,8585.35 2389.65,8522.57 2425,8487.22 R71.1 ; REG4.1@2344.99,8810.78 REG4.1
NetD4_A: D4.A D6.K D7.K Q1.C R28.1 R30.2 U2.3 | length 2058.9
  Bottom Layer w30: Q1.C 1975,10000 2125,10150 2125,10175 2200,10250 2525,10250 D7.K 2611.48,10186.48 2670.24,10186.48 2683.76,10200 R30.2 D4.A 2900,10400 2900,10475 ; D6.K 2900,10475 ; R28.1 3000,10475 ; U2.3 3325,10375 3225,10475 3000,10475 ; 2900,10475 3000,10475
NetD4_K: D4.K D6.A D8.K Q2.C R28.2 R32.2 U2.2 | length 1773
  Top Layer w30: Q2.C 2091.24,9850 2112.38,9871.14 2121.14,9871.14 v1(2225,9975)
  Bottom Layer w30: v1(2225,9975) 2350,10100 2561.48,10100 2662.05,9999.43 2799.43,9999.43 2811.48,10011.48 2870.24,10011.48 2883.76,10025 R32.2 D8.K R28.2 ; D6.A R28.2@2970.24,10225 ; R28.2@2983.76,10225 R28.2 ; U2.2 3225,10378.86 3178.86,10425 3057.43,10425 3000,10367.57 R28.2
NetD13_1: D13.1 L3.2 U3.4 | length 612.1
  Bottom Layer w60: L3.2 D13.1 3350,7775 3495.58,7920.58 3495.58,7995.58 U3.4
NetD15_A: D15.A D17.K R31.1 U1.1 U1.2 | length 964.9
  Top Layer w30: D17.K 2636.48,9313.52 2686.48,9313.52 2699.99,9300.01 2875,9125 2950,9125 U1.1
  Bottom Layer w30: R31.1 2637.5,9425 2650,9412.5 ; R31.1@2525,9450 R31.1@2531.24,9456.24 ; D17.K 2650,9350 2650,9412.5 ; D15.A@2633.76,9475 D15.A 2650,9412.5 ; U1.1 U1.2
NetP3_1: P3.1 RL1.1 Z5.K | length 964.1
  Bottom Layer w30: RL1.1@625,9700 497.57,9700 450,9652.43 458.57,9643.85 458.57,9578.93 562.5,9475 712.37,9475 812.37,9375 925,9375 P3.1
NetP3_2: P3.2 R10.1 | length 432
  Bottom Layer w30: R10.1@625,9062.37 787.37,9062.37 925,9200 P3.2
NetP5_2: P5.2 R42.1 | length 370.7
  Bottom Layer w30: P5.2 3150,11200 3200,11150 R42.1
NetP10_2: P10.2 R12.2 R13.2 | length 2194.3
  Top Layer w30: v1(370,10310) v1(487.5,10310)
  Bottom Layer w30: v1(370,10310) 370,9605 475,9500 475,9400 450,9375 450,9250 475,9225 475,8950 P10.2 ; v1(487.5,10310) 620,10310 690,10380 R12.2 R13.2
NetQ1_E: Q1.E R1.1 R1.2 R17.1 R22.1 | length 2211.3
  Top Layer w30: R22.1@2350,10200 2464.36,10314.36 2519.83,10314.36 2600,10394.53 2600,10475 2675,10550 2825,10550 2950,10675 v1(2950,10800)
  Bottom Layer w30: Q1.E 2216.36,10141.36 R17.1@2216.36,10175 ; R17.1 R22.1 ; v1(2950,10800) 2950,11225 3025,11300 3129.08,11300 3146.66,11317.57 3146.66,11436.66 R1.2 ; R1.2@3150,11439.9 3249.9,11439.9 R1.1
NetR1_3: R1.3 R24.1 | length 191.6
  Bottom Layer w30: R24.1 3010,11400 R1.3
NetR9_1: R9.1 RL1.7 | length 396.7
  Bottom Layer w30: RL1.7 909.57,9990.43 909.57,9945.79 930.36,9925 1077.47,9925 1110,9957.53 R9.1 ; RL1.7@925,9976.47 RL1.7@925,10000
NetR9_2: R9.2 RL1.4 | length 380.7
  Bottom Layer w30: RL1.4 900,9750 925,9775 1085,9775 1110,9750 R9.2
NetR35_2: R35.2 U3.1 | length 280.6
  Bottom Layer w30: U3.1@3375,8200 U3.1 3390,8195 3495,8300 R35.2
NetR36_1: R36.1 R37.2 U3.2 | length 1000.9
  Bottom Layer w30: R36.1 R37.2 2700,8175 3145,8175 3216.47,8103.53 3278.53,8103.53 3305,8130 U3.2
NetZ1_A: Z1.A Z4.A | length 145.2
  Bottom Layer w30: Z4.A 1375,10162.5 1460,10247.5 Z1.A
NetZ2_A: Z2.A Z3.A | length 100
  Bottom Layer w30: Z3.A Z2.A
pads on no net: RL1.5 RL1.6

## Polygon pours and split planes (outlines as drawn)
GND on Top Layer "GND_L01_P000" (solid, pour order 0): 375,11300 600,11300 600,11550 3400,11550 3400,11300 3625,11300 3625,7300 375,7300

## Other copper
Top Layer:
  pour cut-out: 3675,8000 3475,8000 3175,7700 3102.5,7700 3025,7622.5 3025,7275 3675,7275
  pour cut-out: 333.89,11346.57 333.89,11027.74 361.19,11000.43 533.48,11000.43 641.96,11108.9 641.96,11350 337.31,11350
  pour cut-out: 3677.5,7273.75 3675,7276.25 3675,7523.75 3375,7523.75 3375,7273.75
  pour cut-out: 650,7271.57 650,7521.57 333.89,7521.57 333.89,7271.57
  pour cut-out: 625.13,11346.57 625.13,11596.57 333.89,11596.57 333.89,11346.57
  pour cut-out: 3675,11350 3672.5,11352.5 3672.5,11600 3382.69,11600 3382.69,11350
  pour cut-out: 2700,8375 3675,8375 3675,8350 2700,8350
  pour cut-out: 3339.34,11375 3672.5,11375 3672.5,10985.64 3339.34,10985.64
  pour cut-out: 645,7507.5 645,7832.5 334.5,7832.5 334.5,7507.5
  pour cut-out: 3690,7325 3690,7822.26 3350,7822.26 3350,7325
Bottom Layer:
  pour cut-out: 3001.87,8300 3839.37,8300 3839.37,8325 3001.87,8325
  pour cut-out: 325,11375 650,11375 650,11000 325,11000
  pour cut-out: 3300,11375 3647.5,11375 3647.5,11000 3300,11000
  pour cut-out: 2040,8400 2043.5,8403.5
  pour cut-out: 650,7500 650,7840 332,7840 332,7500
  pour cut-out: 3686.25,7470 3686.25,7825 3350,7825 3350,7470

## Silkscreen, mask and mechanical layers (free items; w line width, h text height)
Top Overlay:
  circle w10: c975.42,8498.79 r60.83
  circle w10: c625,8500 r60.83
  circle w10: c1300,11425 r60.83
  circle w10: c625,8025 r60.83
  circle w10: c3525,11175 r150
  circle w10: c475,11175 r150
  circle w10: c475,7650 r150
  circle w10: c3525,7650 r150
  lines w10: 550,11595 550,11375 325,11375 325,7500 550,7500 550,7275 3450,7275 3450,7500 3675,7500 3675,11375 3450,11375 3450,11600 2800,11600 850,11600 550,11600 ; 1900,7325 1900,7575 2425,7575 2425,7325 1900,7325
  text "Ground" at 958,11508 h50
  text "Hot" at 958,11383 h50
  text "GND" at 1233,11308 h40
  text "Cold" at 958,11283 h50
  text "Silicon Chip" at 1480,11129.99 h60
  text "A K" at 3290,11060 h60 r90
  text "Microphone Preamp" at 1480,10985 h60
  text "P/N: 01110232" at 1480,10835 h60
  text "# 1N4148" at 2865,10598 h45 r90
  text "* 1N4004" at 2932,10598 h45 r90
  text "63V" at 790.43,10510.72 h55
  text "63V" at 435.43,10460.72 h55
  text "#" at 2811.39,10435.05 h50
  text "#" at 3053.14,10165.05 h50
  text "#" at 2848,10071.35 h50
  text "#" at 2583,10033 h50
  text "#" at 2858,9603 h50
  text "#" at 2833,9378 h50
  text "#" at 2698,9358 h50
  text "63V" at 1533,9273 h40
  text "63V" at 535.43,9160.72 h55
  text "#" at 2701.77,9128.01 h50
  text "*" at 3433,9124.67 h50
  text "*" at 2043,9099.67 h50
  text "C" at 1747.19,9078.85 h50
  text "H" at 1847.19,9078.85 h50
  text "G" at 1947.19,9078.85 h50
  text "*" at 1507.35,8974.67 h50
  text "63V" at 763,8841.67 h55
  text "63V" at 808,8753 h45
  text "*" at 2256.52,8604.06 h50
  text "*" at 1649.24,8540.41 h50
  text "*" at 3488,8454.67 h50
  text "+11V" at 710,8435 h50
  text "-11V" at 1048.52,8435 h50
  text "GND" at 558,7908 h40
  text "TGM was here" at 1923,7508 h40
  text "V2.1" at 1933,7433 h40
  text "GND" at 1367,7358 h40 r90
  text "2023-05" at 1923,7358 h40
  text "63V" at 2548.43,7358 h55
  text "-15V" at 1267,7333 h40 r90
  text "+15V" at 1467,7333 h40 r90
Mechanical 15:
  lines w10: 325,7500 325,11375 550,11375 550,11600 3450,11600 3450,11375 3675,11375 3675,7500 3450,7500 3450,7275 550,7275 550,7500 325,7500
